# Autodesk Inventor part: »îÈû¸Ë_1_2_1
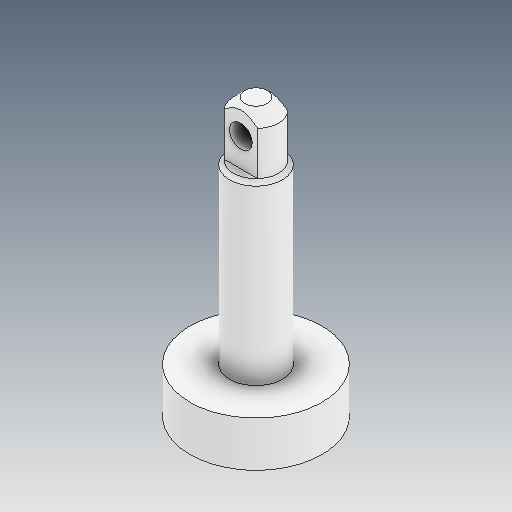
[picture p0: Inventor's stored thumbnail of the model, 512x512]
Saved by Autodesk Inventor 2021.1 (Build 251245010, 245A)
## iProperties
Created: 2021-05
Part Number: »îÈû¸Ë_1_2_1
Material: Ogólny
Document SubType Name: Modeling
Designer: user
Density: 1 g/cm^3
Appearance: Domyślna
Author: user
Revision Number: ÈÎºÎ
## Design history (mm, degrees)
feature "ÊäÈë1"
node "Bryła1"
